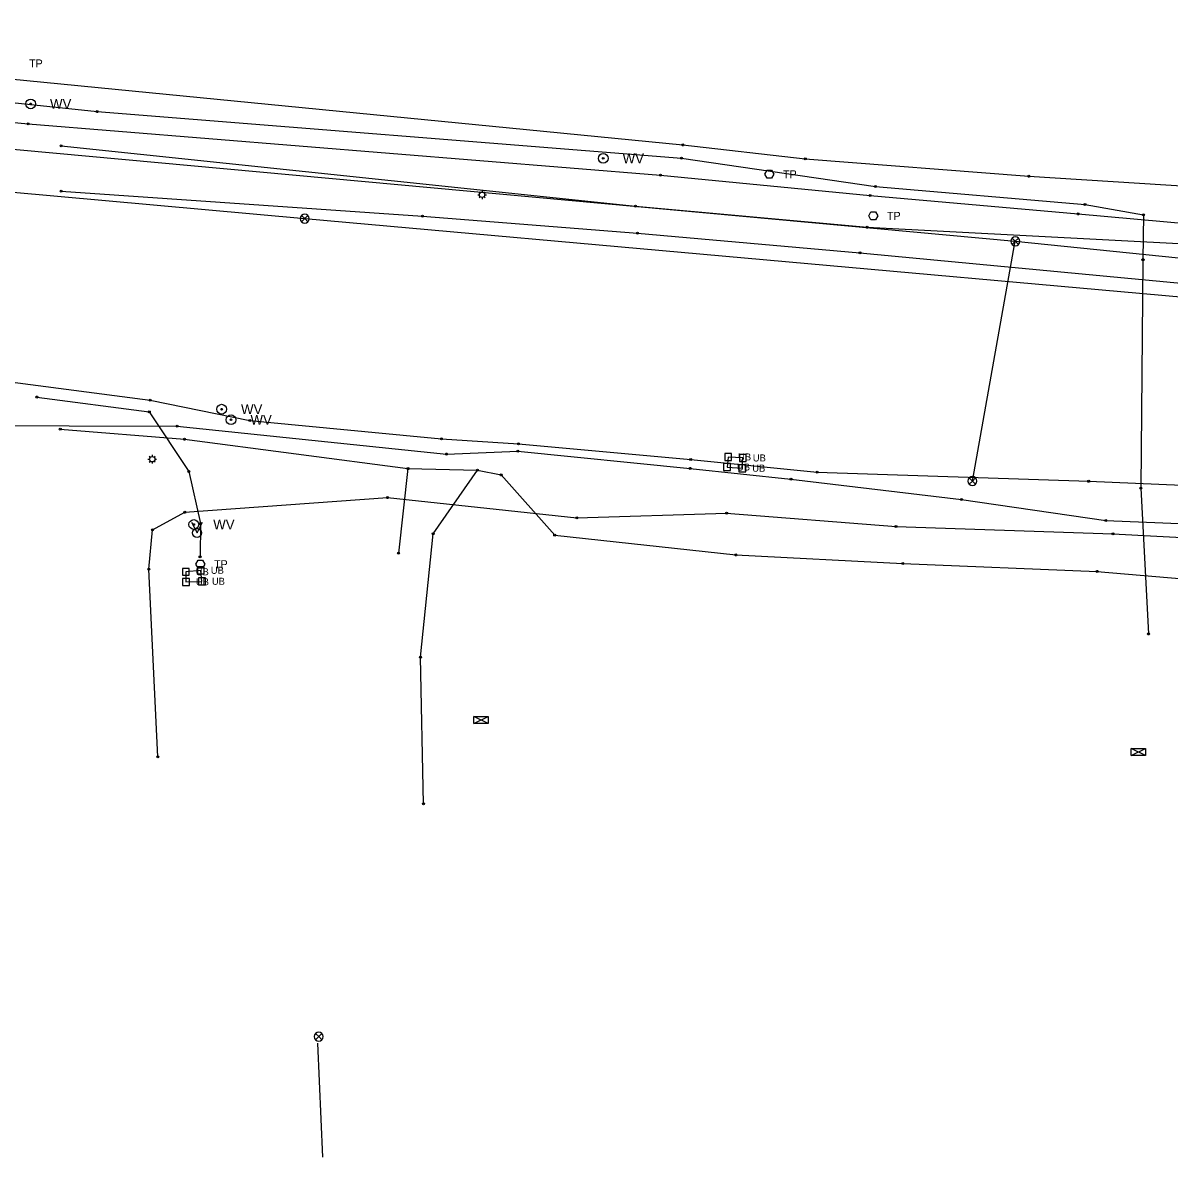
# Model space of a CAD drawing. Extents: x 20500343 to 20505311, y 7953484 to 7954193.
# Drawn here: x 20500534.8 to 20500764, y 7953817.6 to 7954047.5 of the extents above; entities that cross this region are included whole.
import ezdxf

# ---------------------------------------------------------------- set-up
doc = ezdxf.new("R2010")
doc.units = 0
for name, color, linetype in [('C-PROP-LINE-LOT', 7, 'Continuous'), ('V-ANNO-NOTE', 7, 'Continuous'), ('V-CTRL-HVPT', 7, 'Continuous'), ('V-MON-FND', 7, 'Continuous'), ('V-SITE-FENC', 7, 'Continuous'), ('V-SSWR-STRC', 7, 'Continuous'), ('VF-NODE-MISC', 7, 'Continuous')]:
    doc.layers.add(name, color=color, linetype=linetype)

msp = doc.modelspace()

# ---------------------------------------------------------------- linework, layer by layer
at = {"layer": 'C-PROP-LINE-LOT'}
msp.add_line((20500593.65, 7953843.69), (20500594.68, 7953820.91), dxfattribs=at)
for points in [[(20500406.13, 7954047.52), (20500473.69, 7954042.07), (20500666.63, 7954023.16), (20500691.11, 7954020.37), (20500735.76, 7954016.9), (20500774.72, 7954014.43), (20500808.62, 7954016.33)], [(20500405.79, 7954044.85), (20500472.72, 7954037.98), (20500549.61, 7954029.82), (20500666.39, 7954020.52), (20500705.15, 7954014.85), (20500746.99, 7954011.28), (20500758.66, 7954009.18), (20500758.57, 7954000.24), (20500758.16, 7953954.61), (20500759.69, 7953925.46)], [(20500406.47, 7954039.57), (20500466.05, 7954034.11), (20500535.84, 7954027.4), (20500662.16, 7954017.11), (20500704.07, 7954013.07), (20500745.63, 7954009.37), (20500792.32, 7954005.22), (20500811.87, 7954003.45), (20500860.59, 7953999.05), (20500920.01, 7953993.63), (20500957.01, 7953989.31), (20500990.1, 7953987.34), (20501028.58, 7953985.6), (20501071.83, 7953984.74), (20501141.27, 7953979.76), (20501204.8, 7953974.46), (20501273.24, 7953968.85)], [(20500408.85, 7954033.69), (20500534.28, 7954022.2), (20500733.06, 7954003.91), (20500967.33, 7953980.02)], [(20500343.29, 7954030.83), (20500591.11, 7954008.44), (20500942.44, 7953977.04), (20500960.49, 7953579.51)], [(20500542.46, 7954022.99), (20500657.16, 7954010.94), (20500703.46, 7954006.71), (20500768.23, 7954003.33), (20500815.45, 7953998.2), (20500888.96, 7953989.5), (20500955.53, 7953983.16), (20501072.58, 7953980.59), (20501105.36, 7953988.74)], [(20500542.46, 7954013.94), (20500614.61, 7954008.93), (20500657.56, 7954005.52), (20500702.03, 7954001.63), (20500823.93, 7953990.08), (20500894.24, 7953984.51), (20500998.83, 7953975.83), (20501086.53, 7953973.45), (20501164.96, 7953976.11), (20501261.79, 7953980.89), (20501339.33, 7953977.27), (20501419.74, 7953970.03), (20501525.89, 7953965.34), (20501551.15, 7953963.49), (20501624.16, 7953957.55)], [(20500724.5, 7953956.02), (20500733.06, 7954003.91)], [(20500520.98, 7953977.28), (20500560.2, 7953972.18), (20500580.11, 7953968.09), (20500618.43, 7953964.47), (20500633.81, 7953963.45), (20500668.21, 7953960.34), (20500693.49, 7953957.8), (20500747.72, 7953955.96), (20500802.14, 7953953.65), (20500876.21, 7953950.48), (20500928.48, 7953945.92), (20500984.31, 7953941.41), (20501068.76, 7953929.07), (20501169.59, 7953917.28), (20501247.95, 7953910.8), (20501285.38, 7953908.94), (20501306.14, 7953908.1), (20501320.57, 7953910.34), (20501331.41, 7953911.48)], [(20500537.56, 7953972.8), (20500560.05, 7953969.85), (20500567.97, 7953957.92), (20500570.28, 7953947.5), (20500570.18, 7953940.87)], [(20500469.9, 7953970.65), (20500505.35, 7953968.7), (20500522.37, 7953967.11), (20500565.63, 7953966.99), (20500619.43, 7953961.41), (20500633.65, 7953961.99), (20500668.11, 7953958.55), (20500688.24, 7953956.38), (20500722.3, 7953952.32), (20500751.12, 7953948.12), (20500793.42, 7953946.39), (20500829.09, 7953943.31), (20500867.84, 7953939.12), (20500927.83, 7953934.54), (20500971.05, 7953923.41), (20500978.23, 7953919.45), (20500994.58, 7953914.36)], [(20500542.27, 7953966.39), (20500567.09, 7953964.35), (20500611.73, 7953958.49), (20500625.61, 7953958.17), (20500630.34, 7953957.23), (20500641.04, 7953945.21), (20500677.24, 7953941.24), (20500710.61, 7953939.53), (20500749.41, 7953937.97), (20500784.55, 7953934.93), (20500831.09, 7953929.74), (20500863.89, 7953925.18), (20500925.53, 7953920.74), (20500962.01, 7953920.15), (20500972.45, 7953919.98), (20500994.6, 7953919.38), (20501012.87, 7953913.32), (20501056.03, 7953910.21), (20501118.83, 7953905.26), (20501155.51, 7953903.82), (20501202, 7953902.86), (20501247.06, 7953903.19), (20501262.67, 7953902.86)], [(20500611.73, 7953958.49), (20500609.85, 7953941.63)], [(20500614.83, 7953891.55), (20500614.25, 7953920.8), (20500616.75, 7953945.5), (20500625.61, 7953958.17)], [(20500561.73, 7953900.93), (20500559.97, 7953938.39), (20500560.68, 7953946.27), (20500567.17, 7953949.77), (20500607.64, 7953952.7), (20500645.48, 7953948.64), (20500675.39, 7953949.59), (20500709.23, 7953946.92), (20500752.57, 7953945.49), (20500788.98, 7953943.53), (20500807.81, 7953941.62), (20500828.86, 7953938.77), (20500890, 7953934.48), (20500927.37, 7953930.61), (20500963.01, 7953925.35), (20500973.65, 7953920.63), (20500978.51, 7953892.75), (20500979.78, 7953871.77)]]:
    msp.add_lwpolyline(points, dxfattribs=at)
at = {"layer": 'V-ANNO-NOTE'}
for centre in [(20500549.61, 7954029.82), (20500535.84, 7954027.4), (20500542.46, 7954022.99), (20500666.63, 7954023.16), (20500666.39, 7954020.52), (20500691.11, 7954020.37), (20500662.16, 7954017.11), (20500735.76, 7954016.9), (20500542.46, 7954013.94), (20500705.15, 7954014.85), (20500704.07, 7954013.07), (20500746.99, 7954011.28), (20500614.61, 7954008.93), (20500657.16, 7954010.94), (20500745.63, 7954009.37), (20500758.66, 7954009.18), (20500703.46, 7954006.71), (20500657.56, 7954005.52), (20500702.03, 7954001.63), (20500758.57, 7954000.24), (20500537.56, 7953972.8), (20500560.2, 7953972.18), (20500560.05, 7953969.85), (20500580.11, 7953968.09), (20500542.27, 7953966.39), (20500565.63, 7953966.99), (20500567.09, 7953964.35), (20500618.43, 7953964.47), (20500633.81, 7953963.45), (20500619.43, 7953961.41), (20500633.65, 7953961.99), (20500611.73, 7953958.49), (20500611.73, 7953958.49), (20500668.11, 7953958.55), (20500668.21, 7953960.34), (20500567.97, 7953957.92), (20500625.61, 7953958.17), (20500625.61, 7953958.17), (20500630.34, 7953957.23), (20500688.24, 7953956.38), (20500693.49, 7953957.8), (20500747.72, 7953955.96), (20500758.16, 7953954.61), (20500607.64, 7953952.7), (20500722.3, 7953952.32), (20500567.17, 7953949.77), (20500675.39, 7953949.59), (20500570.28, 7953947.5), (20500645.48, 7953948.64), (20500709.23, 7953946.92), (20500751.12, 7953948.12), (20500560.68, 7953946.27), (20500616.75, 7953945.5), (20500641.04, 7953945.21), (20500752.57, 7953945.49), (20500570.18, 7953940.87), (20500609.85, 7953941.63), (20500677.24, 7953941.24), (20500559.97, 7953938.39), (20500710.61, 7953939.53), (20500749.41, 7953937.97), (20500759.69, 7953925.46), (20500614.25, 7953920.8), (20500561.73, 7953900.93), (20500614.83, 7953891.55)]:
    msp.add_circle(centre, 0.2, dxfattribs=at)
at = {"layer": 'V-CTRL-HVPT'}
for p, q in [((20500625.93, 7954013.82), (20500626.16, 7954013.59)), ((20500626.54, 7954014.07), (20500626.54, 7954013.75)), ((20500626.92, 7954013.59), (20500627.15, 7954013.82)), ((20500625.67, 7954013.2), (20500626, 7954013.2)), ((20500625.93, 7954012.59), (20500626.16, 7954012.82)), ((20500626.54, 7954012.66), (20500626.54, 7954012.33)), ((20500626.92, 7954012.82), (20500627.15, 7954012.59)), ((20500627.08, 7954013.2), (20500627.41, 7954013.2)), ((20500560.03, 7953960.99), (20500560.26, 7953960.76)), ((20500560.64, 7953961.24), (20500560.64, 7953960.92)), ((20500561.02, 7953960.76), (20500561.25, 7953960.99)), ((20500559.77, 7953960.37), (20500560.1, 7953960.37)), ((20500560.03, 7953959.76), (20500560.26, 7953959.99)), ((20500560.64, 7953959.83), (20500560.64, 7953959.5)), ((20500561.02, 7953959.99), (20500561.25, 7953959.76)), ((20500561.18, 7953960.37), (20500561.51, 7953960.37))]:
    msp.add_line(p, q, dxfattribs=at)
for centre in [(20500626.54, 7954013.2), (20500560.64, 7953960.37)]:
    msp.add_circle(centre, 0.543, dxfattribs=at)
at = {"layer": 'V-MON-FND'}
for points in [[(20500683.01, 7954017.3), (20500683.46, 7954018.1), (20500684.38, 7954018.1), (20500684.83, 7954017.3), (20500684.38, 7954016.51), (20500683.46, 7954016.51), (20500683.01, 7954017.3)], [(20500703.77, 7954009), (20500704.22, 7954009.79), (20500705.14, 7954009.79), (20500705.59, 7954009), (20500705.14, 7954008.2), (20500704.22, 7954008.2), (20500703.77, 7954009)], [(20500569.34, 7953939.39), (20500569.79, 7953940.18), (20500570.71, 7953940.18), (20500571.16, 7953939.39), (20500570.71, 7953938.59), (20500569.79, 7953938.59), (20500569.34, 7953939.39)]]:
    msp.add_lwpolyline(points, dxfattribs=at)
for points in [[(20500675.47, 7953958.8), (20500678.52, 7953958.56), (20500678.63, 7953960.62), (20500675.69, 7953960.81)], [(20500675.47, 7953958.8), (20500678.52, 7953958.56), (20500678.63, 7953960.62), (20500675.69, 7953960.81)], [(20500567.37, 7953935.86), (20500570.57, 7953935.97), (20500570.35, 7953938.16), (20500567.34, 7953937.87)], [(20500567.37, 7953935.86), (20500570.57, 7953935.97), (20500570.35, 7953938.16), (20500567.34, 7953937.87)]]:
    msp.add_lwpolyline(points, close=True, dxfattribs=at)
at = {"layer": 'V-SITE-FENC'}
for points in [[(20500675.69, 7953960.13), (20500675.69, 7953960.13), (20500676.38, 7953960.13), (20500676.38, 7953961.5), (20500675, 7953961.5), (20500675, 7953960.13), (20500675.69, 7953960.13)], [(20500678.63, 7953959.93), (20500678.63, 7953959.93), (20500679.32, 7953959.93), (20500679.32, 7953961.3), (20500677.94, 7953961.3), (20500677.94, 7953959.93), (20500678.63, 7953959.93)], [(20500675.47, 7953958.11), (20500675.47, 7953958.11), (20500676.16, 7953958.11), (20500676.16, 7953959.49), (20500674.78, 7953959.49), (20500674.78, 7953958.11), (20500675.47, 7953958.11)], [(20500678.52, 7953957.87), (20500678.52, 7953957.87), (20500679.21, 7953957.87), (20500679.21, 7953959.24), (20500677.83, 7953959.24), (20500677.83, 7953957.87), (20500678.52, 7953957.87)], [(20500567.34, 7953937.19), (20500567.34, 7953937.19), (20500568.03, 7953937.19), (20500568.03, 7953938.56), (20500566.65, 7953938.56), (20500566.65, 7953937.19), (20500567.34, 7953937.19)], [(20500570.35, 7953937.48), (20500570.35, 7953937.48), (20500571.04, 7953937.48), (20500571.04, 7953938.85), (20500569.66, 7953938.85), (20500569.66, 7953937.48), (20500570.35, 7953937.48)], [(20500567.37, 7953935.17), (20500567.37, 7953935.17), (20500568.06, 7953935.17), (20500568.06, 7953936.55), (20500566.68, 7953936.55), (20500566.68, 7953935.17), (20500567.37, 7953935.17)], [(20500570.57, 7953935.28), (20500570.57, 7953935.28), (20500571.26, 7953935.28), (20500571.26, 7953936.66), (20500569.88, 7953936.66), (20500569.88, 7953935.28), (20500570.57, 7953935.28)]]:
    msp.add_lwpolyline(points, dxfattribs=at)
at = {"layer": 'V-SSWR-STRC'}
for points in [[(20500590.47, 7954007.8), (20500591.11, 7954008.44), (20500590.47, 7954009.07)], [(20500591.75, 7954009.07), (20500591.11, 7954008.44), (20500591.75, 7954007.8)], [(20500732.42, 7954003.27), (20500733.06, 7954003.91), (20500732.42, 7954004.54)], [(20500733.7, 7954004.54), (20500733.06, 7954003.91), (20500733.7, 7954003.27)], [(20500723.86, 7953955.39), (20500724.5, 7953956.02), (20500723.86, 7953956.66)], [(20500725.14, 7953956.66), (20500724.5, 7953956.02), (20500725.14, 7953955.39)], [(20500624.89, 7953907.56), (20500627.77, 7953909), (20500627.77, 7953907.56), (20500624.89, 7953909)], [(20500756.18, 7953901.17), (20500759.06, 7953902.61), (20500759.06, 7953901.17), (20500756.18, 7953902.61)], [(20500593.25, 7953844.38), (20500593.89, 7953845.01), (20500593.25, 7953845.65)], [(20500594.53, 7953845.65), (20500593.89, 7953845.01), (20500594.53, 7953844.38)]]:
    msp.add_lwpolyline(points, dxfattribs=at)
for points in [[(20500624.89, 7953907.56), (20500624.89, 7953909), (20500627.77, 7953909), (20500627.77, 7953907.56)], [(20500756.18, 7953901.17), (20500756.18, 7953902.61), (20500759.06, 7953902.61), (20500759.06, 7953901.17)]]:
    msp.add_lwpolyline(points, close=True, dxfattribs=at)
for centre, radius in [((20500536.33, 7954031.37), 0.971), ((20500536.33, 7954031.37), 0.162), ((20500650.73, 7954020.48), 0.971), ((20500650.73, 7954020.48), 0.162), ((20500574.49, 7953970.37), 0.971), ((20500574.49, 7953970.37), 0.162), ((20500576.38, 7953968.25), 0.971), ((20500576.38, 7953968.25), 0.162), ((20500568.94, 7953947.33), 0.971), ((20500568.94, 7953947.33), 0.162)]:
    msp.add_circle(centre, radius, dxfattribs=at)
for centre, start, end in [((20500591.11, 7954008.44), 135, 225), ((20500591.11, 7954008.44), 45, 135), ((20500591.11, 7954008.44), 315, 45), ((20500591.11, 7954008.44), 225, 315), ((20500733.06, 7954003.91), 135, 225), ((20500733.06, 7954003.91), 45, 135), ((20500733.06, 7954003.91), 315, 45), ((20500733.06, 7954003.91), 225, 315), ((20500724.5, 7953956.02), 135, 225), ((20500724.5, 7953956.02), 45, 135), ((20500724.5, 7953956.02), 315, 45), ((20500724.5, 7953956.02), 225, 315), ((20500593.89, 7953845.01), 45, 135), ((20500593.89, 7953845.01), 135, 225), ((20500593.89, 7953845.01), 225, 315), ((20500593.89, 7953845.01), 315, 45)]:
    msp.add_arc(centre, 0.899, start, end, dxfattribs=at)
at = {"layer": 'VF-NODE-MISC'}
for p, q in [((20500568.51, 7953947.82), (20500569.59, 7953945.66)), ((20500569.59, 7953945.66), (20500570.67, 7953947.82))]:
    msp.add_line(p, q, dxfattribs=at)
msp.add_circle((20500569.59, 7953945.66), 0.897, dxfattribs=at)

# ---------------------------------------------------------------- texts
at = {"layer": 'V-MON-FND'}
for p in [(20500536.03, 7954038.65), (20500686.66, 7954016.5), (20500707.42, 7954008.2), (20500572.99, 7953938.59)]:
    msp.add_text('TP', height=1.599, dxfattribs=at).set_placement(p)
at = {"layer": 'V-SITE-FENC'}
for p in [(20500677.68, 7953960.13), (20500680.62, 7953959.93), (20500677.46, 7953958.12), (20500680.51, 7953957.88), (20500569.33, 7953937.19), (20500572.34, 7953937.48), (20500569.36, 7953935.18), (20500572.56, 7953935.29)]:
    msp.add_text('UB', height=1.399, dxfattribs=at).set_placement(p)
at = {"layer": 'V-SSWR-STRC'}
for p in [(20500540.21, 7954030.38), (20500654.61, 7954019.49), (20500578.37, 7953969.38), (20500580.26, 7953967.26), (20500572.82, 7953946.34)]:
    msp.add_text('WV', height=1.982, dxfattribs=at).set_placement(p)

doc.saveas('drawing.dxf')
